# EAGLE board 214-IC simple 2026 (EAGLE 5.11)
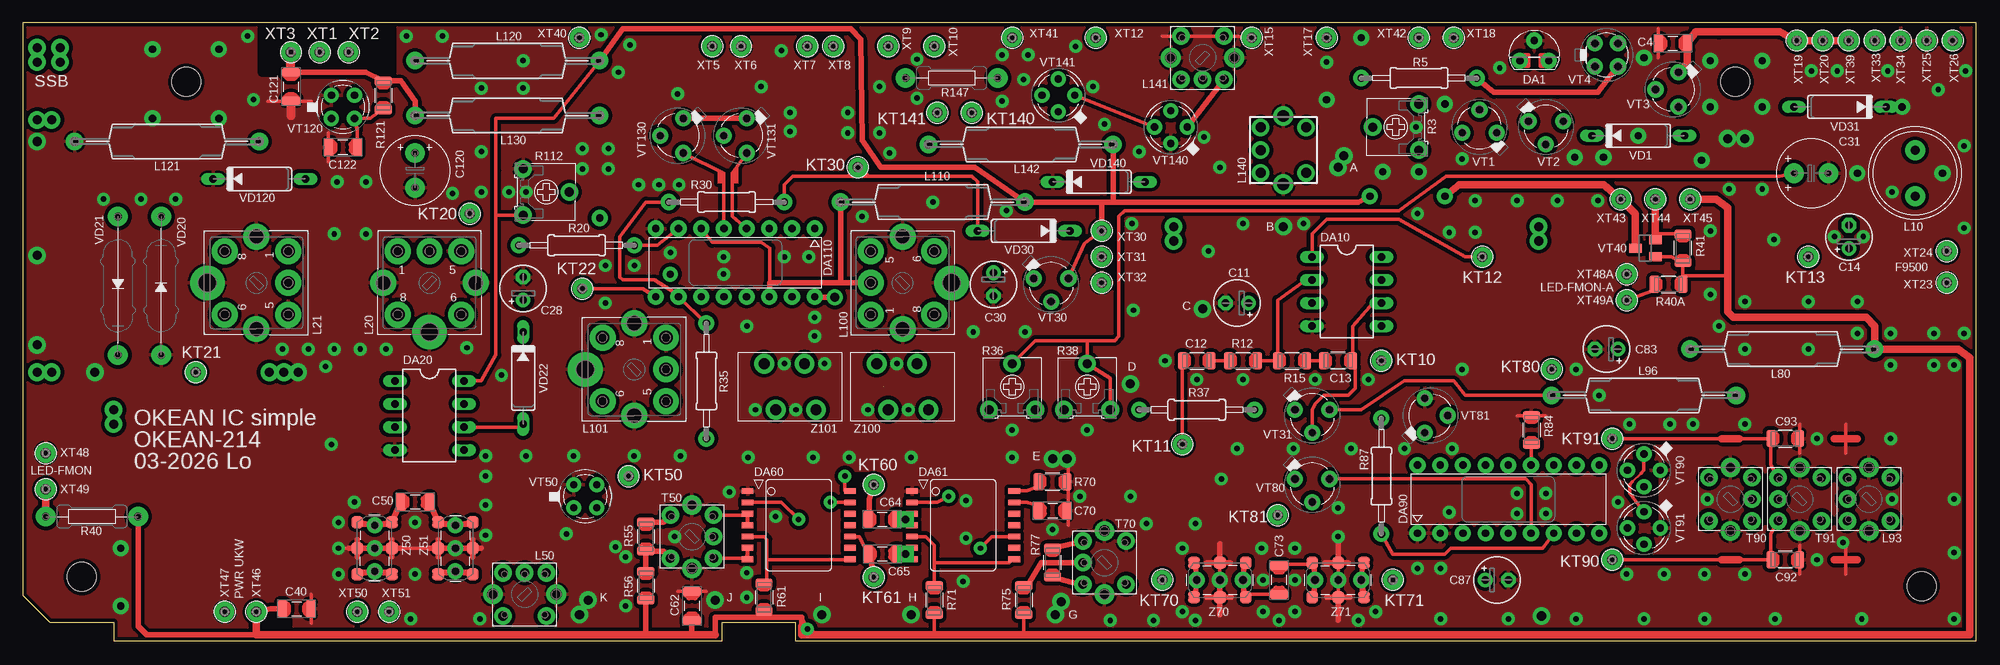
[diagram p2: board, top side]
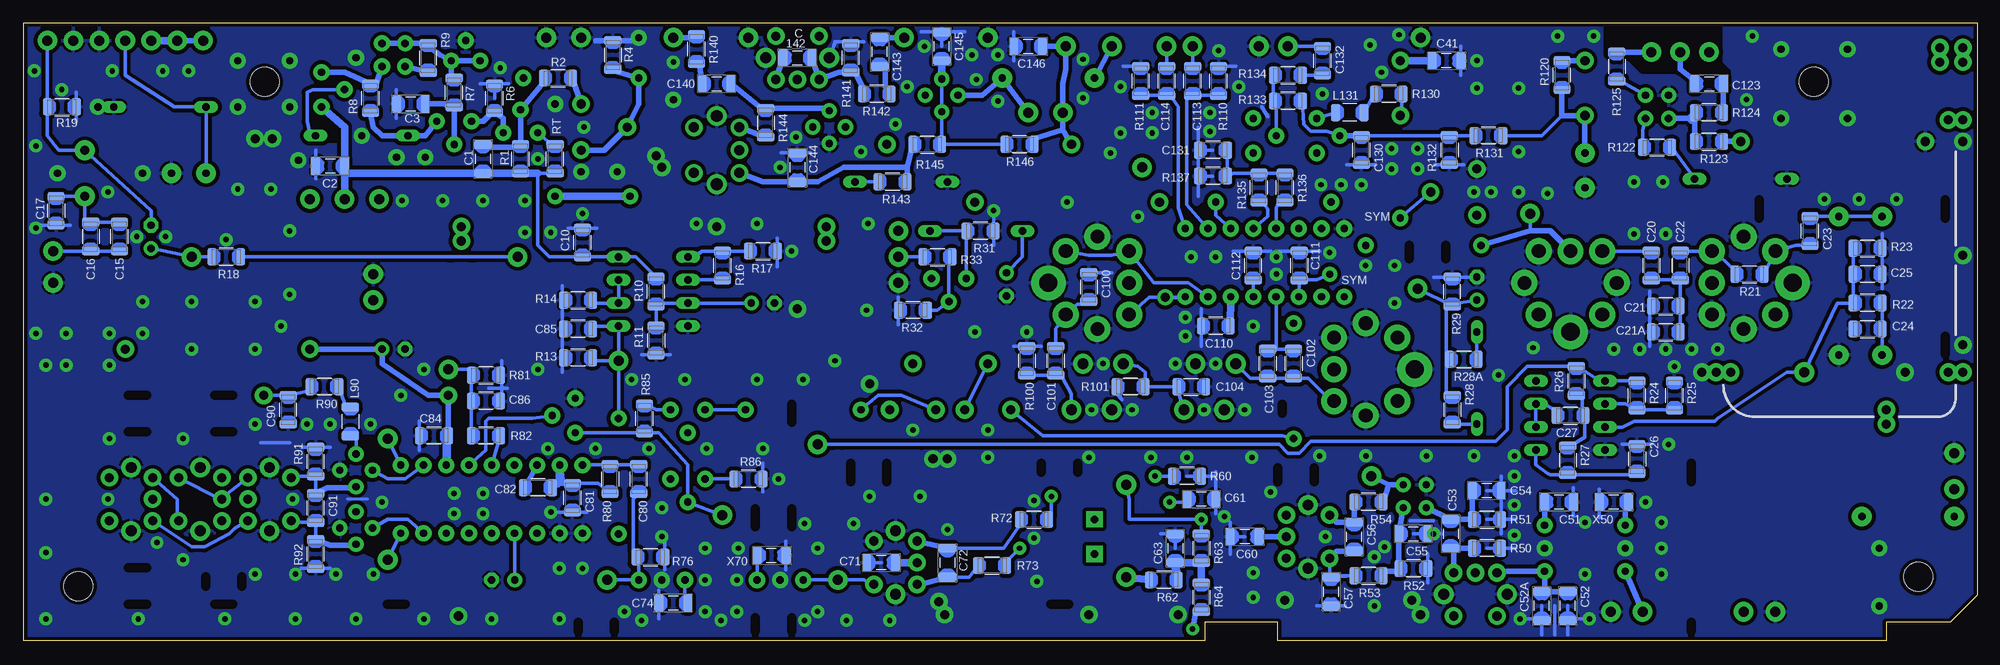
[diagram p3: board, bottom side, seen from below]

Size 215 x 68 mm. Coordinates in mm from the lower left corner, seen from the top.
Outline: 3,2 10,2 10,0 77,0 77,2 85,2 85,0 215,0 215,68 0,68 0,5 3,2
Copper layers (1*16): Top 0.035mm / dielectric 1.5mm / Bottom 0.035mm
Design rules "default *": minimum track width 10mil, minimum drill 24mil, track to track 8mil, track to pad 8mil, pad to pad 8mil, via to via 8mil, smd to smd 8mil, copper to edge 8mil, drill to drill 8mil, minimum pad ring 10mil, minimum via ring 8mil, stop-mask expansion 4mil, vias tented up to drill 0mil, thermal gap 10mil
Holes 3.2 mm at 6.5,7 18,61.5 188.5,61.5 209,6
tRestrict: area 85,29.5 to 87,31.5; area 81.9,24.4 to 83.8,26.4; area 97.4,29.5 to 99.4,31.5; area 94.2,24.4 to 96.3,26.4; 21 lines
bRestrict: 75 lines

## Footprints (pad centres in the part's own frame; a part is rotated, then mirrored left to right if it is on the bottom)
RC-SMD-UNIV = smd 0.965 x 1.93: P$1 -1.587,0; P$2 1.587,0
C1206 = smd 1 x 1.905: 1 -1.587,0; 2 1.587,0
E2,5-5 = drill 0.813 pad 1.6 round: + -1.27,0 | drill 0.813 pad 1.6 octagon: - 1.27,0
C-ELKO-038-075 = drill 0.8 pad 2.184 round: P$1 -1.905,0; P$2 1.905,0
TO92 = drill 0.8 pad 1.778 round: 1 -1.587,-0.635; 2 0,1.587; 3 1.587,-0.635
DIL08 = drill 0.813 long: 1 -3.81,-3.81; 2 -1.27,-3.81; 3 1.27,-3.81; 4 3.81,-3.81; 5 3.81,3.81; 6 1.27,3.81; 7 -1.27,3.81; 8 -3.81,3.81
401.14-5M-FP = smd 0.635 x 1.27: P$1 -3.75,-5.625; P$2 -2.5,-5.625; P$3 -1.25,-5.625; P$4 0,-5.625; P$5 1.25,-5.625; P$6 2.5,-5.625; P$7 3.75,-5.625; P$8 3.75,5.625; P$9 2.5,5.625; P$10 1.25,5.625; P$11 0,5.625; P$12 -1.25,5.625; P$13 -2.5,5.625; P$14 -3.75,5.625
174XA-CERDIP-18 = drill 0.8 pad 1.778 round: P$1 -10,-3.75; P$2 -7.5,-3.75; P$3 -5,-3.75; P$4 -2.5,-3.75; P$5 0,-3.75; P$6 2.5,-3.75; P$7 5,-3.75; P$8 7.5,-3.75; P$9 10,-3.75; P$10 10,3.75; P$11 7.5,3.75; P$12 5,3.75; P$13 2.5,3.75; P$14 0,3.75; P$15 -2.5,3.75; P$16 -5,3.75; P$17 -7.5,3.75; P$18 -10,3.75
174XA2-CERDIP-16 = drill 0.8 pad 1.778 round: P$1 -8.75,-3.75; P$2 -6.25,-3.75; P$3 -3.75,-3.75; P$4 -1.25,-3.75; P$5 1.25,-3.75; P$6 3.75,-3.75; P$7 6.25,-3.75; P$8 8.75,-3.75; P$9 8.75,3.75; P$10 6.25,3.75; P$11 3.75,3.75; P$12 1.25,3.75; P$13 -1.25,3.75; P$14 -3.75,3.75; P$15 -6.25,3.75; P$16 -8.75,3.75
SE11 = drill 1.1 pad 2.159 round: MP 0,0
TOKO-RB10 = drill 1 pad 2.184 round: P$1 2.54,0; P$2 -2.54,0
L-12-10 = drill 1.5 pad 2.852 round: 1 3.493,-3.493; 3 0,-3.493; 5 -3.493,-3.493; 6 -3.493,3.493; 8 3.493,3.493; 11 -5.08,0; 14 5.08,0 | drill 2 pad 3.81 round: 15 0,5.397
L-7-MM = drill 1 pad 1.93 round: 1 -2.381,-2.381; 2 0,-2.381; 3 2.381,-2.381; 4 2.381,2.381; 5 -2.381,2.381 | drill 1.2 pad 2.184 round: P$6 3.493,0; P$7 -3.493,0
0309/20-RUSS = drill 1 pad 1.93 round: 1 -10.16,0; 2 10.16,0
L1206 = smd 1 x 1.905: 1 -1.587,0; 2 1.587,0
71-5 = drill 1.1 pad 1.93 round: 1 2.5,-2.5; 2 2.5,2.5; 3 0,2.5; 4 -2.5,2.5; 5 -2.5,-2.5 | drill 1.3 pad 2.184 round: S1 -3.75,0; S2 3.75,0
R1206 = smd 1 x 1.905: 1 -1.587,0; 2 1.587,0
CA6-V = drill 1 pad 1.93 round: A 2.54,-2.54; E -2.54,-2.54; S 0,2.54
0207/12 = drill 0.813 pad 1.778 round: 1 -6.35,0; 2 6.35,0
R-10 = drill 0.8 pad 2.184 round: P$1 -5.08,0; P$2 5.08,0
DO07 = drill 0.813 long: A 5.08,0; C -5.08,0
VD-OLD-GLASS = drill 0.8 pad 2.184 round: P$1 -7.62,0; P$2 7.62,0
VT-TO-18-3 = drill 0.8 pad 1.778 round: 1 1.905,-0.635; 2 0,1.905; 3 -1.905,-0.635
VT-TO-18-4 = drill 0.8 pad 1.778 round: 1 1.27,-1.27; 2 1.27,1.27; 3 -1.27,1.27; 4 -1.27,-1.27
SOT23 = smd 1 x 1.4: 1 -0.95,-1.1; 2 0.95,-1.1; 3 0,1.1
TO72B = drill 0.8 pad 1.676 round: B 1.27,-1.27; C 1.27,1.27; E -1.27,-1.27; GEH -1.27,1.27
PKF-10700-U-N = drill 0.8 pad 1.778 round: P$1 -2.54,0; P$4 0,0; P$7 2.54,0 | smd 1.27 x 1.27: P$2 -2.857,-1.905; P$3 -2.857,1.905; P$5 0,-1.905; P$6 0,1.905; P$8 2.857,-1.905; P$9 2.857,1.905
FP1P1-60 = drill 1.2 pad 2.184 round: 1 -2.54,2.54; 2 3.175,-2.54; 3 1.905,2.54; 4 -1.27,-2.54

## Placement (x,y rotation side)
C1  [RC-SMD-UNIV]  164.47,53.02 90 bottom
C2  [RC-SMD-UNIV]  181.29,52.23 180 bottom
C3  [RC-SMD-UNIV]  172.4,59.05 180 bottom
C4  [RC-SMD-UNIV]  181.61,65.72 0 top
C10  [C1206]  153.52,43.82 90 bottom
C11  [E2,5-5]  133.67,37.15 180 top
C12  [C1206]  129.22,30.8 0 top
C13  [C1206]  144.78,30.8 180 top
C14  [E2,5-5]  200.99,44.44 90 top
C15  [C1206]  204.47,44.45 90 bottom
C16  [C1206]  207.65,44.45 270 bottom
C17  [C1206]  211.46,47.31 270 bottom
C20  [C1206]  35.88,41.27 270 bottom
C21  [C1206]  34.29,36.83 0 bottom
C21A  [C1206]  34.29,33.97 0 bottom
C22  [C1206]  32.7,41.27 270 bottom
C23  [C1206]  18.41,45.09 90 bottom
C24  [C1206]  12.06,34.29 0 bottom
C25  [C1206]  12.06,40.32 180 bottom
C26  [C1206]  37.47,20 270 bottom
C27  [C1206]  44.77,24.77 0 bottom
C28  [E2,5-5]  55.09,38.74 90 top
C30  [E2,5-5]  106.84,39.21 270 top
C31  C-ELKO-038-075  [C-ELKO-038-075]  196.85,51.44 180 top
C40  [RC-SMD-UNIV]  30.16,3.49 180 top
C41  [RC-SMD-UNIV]  58.42,63.82 0 bottom
C50  [RC-SMD-UNIV]  43.18,15.24 0 top
C51  [RC-SMD-UNIV]  46.04,15.24 180 bottom
C52  [RC-SMD-UNIV]  45.09,3.81 270 bottom
C52A  [RC-SMD-UNIV]  47.94,3.81 270 bottom
C53  [RC-SMD-UNIV]  57.94,11.75 270 bottom
C54  [RC-SMD-UNIV]  53.98,16.51 180 bottom
C55  [RC-SMD-UNIV]  62.07,11.75 0 bottom
C56  [RC-SMD-UNIV]  68.58,11.43 90 bottom
C57  [RC-SMD-UNIV]  71.12,5.4 90 bottom
C60  [RC-SMD-UNIV]  80.64,11.43 0 bottom
C61  [RC-SMD-UNIV]  85.41,15.56 0 bottom
C62  [RC-SMD-UNIV]  73.66,3.81 270 top
C63  [RC-SMD-UNIV]  88.27,10.16 90 bottom
C64  [RC-SMD-UNIV]  94.61,13.34 180 top
C65  [RC-SMD-UNIV]  94.61,9.53 0 top
C70  [RC-SMD-UNIV]  113.35,14.29 180 top
C71  [RC-SMD-UNIV]  120.65,8.57 0 bottom
C72  [RC-SMD-UNIV]  113.35,8.57 90 bottom
C73  [RC-SMD-UNIV]  138.27,6.67 90 top
C74  [RC-SMD-UNIV]  143.51,4.13 180 bottom
C80  [C1206]  147.32,17.78 90 bottom
C81  [C1206]  154.62,15.72 90 bottom
C82  [C1206]  158.43,16.83 180 bottom
C83  [E2,5-5]  174.31,32.07 180 top
C84  [C1206]  169.86,22.54 180 bottom
C85  [C1206]  153.99,34.29 180 bottom
C86  [C1206]  164.15,26.35 180 bottom
C87  [E2,5-5]  162.24,6.67 0 top
C90  [C1206]  185.9,25.4 90 bottom
C91  [C1206]  182.88,14.61 90 bottom
C92  [C1206]  193.99,8.89 180 top
C93  [C1206]  193.99,22.23 0 top
C100  [C1206]  97.79,38.89 270 bottom
C101  [C1206]  101.44,30.8 270 bottom
C102  [C1206]  75.25,30.48 270 bottom
C103  [C1206]  78.11,30.48 270 bottom
C104  [C1206]  86.52,27.94 0 bottom
C110  [C1206]  83.82,34.61 180 bottom
C111  [C1206]  74.61,41.27 90 bottom
C112  [C1206]  79.69,41.27 90 bottom
C113  [C1206]  86.36,61.59 90 bottom
C114  [C1206]  89.22,61.59 90 bottom
C120  C-ELKO-038-075  [C-ELKO-038-075]  43.18,51.75 90 top
C121  [RC-SMD-UNIV]  29.53,60.96 270 top
C122  [RC-SMD-UNIV]  35.24,54.29 0 top
C123  [RC-SMD-UNIV]  29.53,61.28 180 bottom
C130  [C1206]  67.79,53.98 90 bottom
C131  [C1206]  84.14,53.98 180 bottom
C132  [C1206]  72.07,63.82 90 bottom
C140  [RC-SMD-UNIV]  138.75,61.28 180 bottom
C142  [RC-SMD-UNIV]  129.86,64.14 180 bottom
C143  [RC-SMD-UNIV]  120.82,64.78 270 bottom
C144  [RC-SMD-UNIV]  129.86,52.07 90 bottom
C145  [RC-SMD-UNIV]  113.98,65.41 90 bottom
C146  [RC-SMD-UNIV]  104.46,65.41 0 bottom
DA1  [TO92]  166.37,64.45 0 top
DA10  [DIL08]  145.73,38.42 270 top
DA20  [DIL08]  44.77,24.77 270 top
DA60  175-UV-4-FP  [401.14-5M-FP]  85.41,12.7 270 top
DA61  175-UV-4-FP  [401.14-5M-FP]  103.5,12.7 270 top
DA90  [174XA-CERDIP-18]  163.51,15.56 0 top
DA110  [174XA2-CERDIP-16]  78.42,41.59 180 top
KT10  SE11  [SE11]  149.54,30.8 270 top
KT11  SE11  [SE11]  127.64,21.59 0 top
KT12  SE11  [SE11]  160.66,42.23 0 top
KT13  SE11  [SE11]  196.53,42.23 0 top
KT20  SE11  [SE11]  49.21,46.99 90 top
KT21  SE11  [SE11]  19.05,29.53 270 top
KT22  SE11  [SE11]  61.6,38.74 0 top
KT30  SE11  [SE11]  91.92,52.07 0 top
KT50  SE11  [SE11]  66.67,18.1 270 top
KT60  SE11  [SE11]  93.66,17.14 0 top
KT61  SE11  [SE11]  93.66,6.99 0 top
KT70  SE11  [SE11]  125.41,6.67 90 top
KT71  SE11  [SE11]  150.81,6.67 270 top
KT80  SE11  [SE11]  168.28,29.84 90 top
KT81  SE11  [SE11]  138.12,13.81 0 top
KT90  SE11  [SE11]  174.94,8.89 90 top
KT91  SE11  [SE11]  174.94,22.23 90 top
KT140  SE11  [SE11]  104.46,58.1 0 top
KT141  SE11  [SE11]  100.65,58.1 0 top
L10  [TOKO-RB10]  208.28,51.44 270 top
L20  [L-12-10]  44.77,39.37 180 top
L21  [L-12-10]  25.72,39.37 90 top
L50  [L-7-MM]  55.24,5.08 180 top
L80  [0309/20-RUSS]  193.68,32.07 180 top
L90  [L1206]  179.07,24.13 270 bottom
L93  [L-7-MM]  203.2,15.56 270 top
L96  [0309/20-RUSS]  178.44,26.99 0 top
L100  [L-12-10]  96.84,39.37 270 top
L101  [L-12-10]  67.31,29.84 90 top
L110  [0309/20-RUSS]  100.17,48.26 180 top
L120  [0309/20-RUSS]  53.34,63.82 180 top
L121  [0309/20-RUSS]  15.88,54.93 180 top
L130  [0309/20-RUSS]  53.34,57.78 0 top
L131  [L1206]  69.06,58.1 180 bottom
L140  71-5-24153  [71-5]  138.75,53.98 90 top
L141  [L-7-MM]  129.86,64.14 0 top
L142  [0309/20-RUSS]  109.86,54.61 180 top
R1  [R1206]  160.34,53.02 90 bottom
R2  [R1206]  156.21,61.91 0 bottom
R3  [CA6-V]  151.13,56.52 90 top
R4  [R1206]  150.18,64.45 270 bottom
R5  [0207/12]  153.67,61.91 180 top
R6  [R1206]  163.19,59.69 90 bottom
R7  [R1206]  167.64,60.33 90 bottom
R8  [R1206]  176.85,59.69 90 bottom
R9  [R1206]  170.5,64.14 90 bottom
R10  [R1206]  145.41,38.42 90 bottom
R11  [R1206]  145.41,33.02 270 bottom
R12  [R1206]  134.3,30.8 0 top
R13  [R1206]  153.99,31.11 180 bottom
R14  [R1206]  153.99,37.47 0 bottom
R15  [R1206]  139.7,30.8 0 top
R16  [R1206]  138.11,41.27 90 bottom
R17  [R1206]  133.67,42.86 0 bottom
R18  [R1206]  192.72,42.23 180 bottom
R19  [R1206]  210.82,58.74 0 bottom
R20  [0207/12]  60.96,43.5 180 top
R21  [R1206]  25.08,40.32 0 bottom
R22  [R1206]  12.06,37.15 180 bottom
R23  [R1206]  12.06,43.18 0 bottom
R24  [R1206]  37.47,26.99 90 bottom
R25  [R1206]  33.34,26.99 90 bottom
R26  [R1206]  44.13,28.57 270 bottom
R27  [R1206]  45.08,19.84 270 bottom
R28  [R1206]  57.78,25.4 270 bottom
R28A  [R1206]  56.52,30.95 0 bottom
R29  [R1206]  57.78,38.41 90 bottom
R30  [0207/12]  77.47,48.26 0 top
R31  [R1206]  109.7,45.09 180 bottom
R32  [R1206]  117.16,36.35 180 bottom
R33  [R1206]  114.46,42.23 0 bottom
R35  [0207/12]  75.25,28.57 270 top
R36  [CA6-V]  108.9,27.94 0 top
R37  [0207/12]  129.22,25.4 0 top
R38  [CA6-V]  117.16,27.94 0 top
R40  R-10  [R-10]  7.62,13.65 0 top
R40A  [R1206]  181.15,39.21 0 top
R41  [R1206]  182.73,43.18 90 top
R50  [R1206]  53.98,10.16 180 bottom
R51  [R1206]  53.98,13.34 0 bottom
R52  [R1206]  62.07,7.94 180 bottom
R53  [R1206]  66.99,7.14 0 bottom
R54  [R1206]  66.99,15.24 180 bottom
R55  [R1206]  68.58,11.43 270 top
R56  [R1206]  68.58,6.03 270 top
R60  [R1206]  87,18.1 180 bottom
R61  [R1206]  81.6,4.76 270 top
R62  [R1206]  89.53,6.67 180 bottom
R63  [R1206]  85.41,10.16 270 bottom
R64  [R1206]  85.41,4.76 270 bottom
R70  [R1206]  113.35,17.46 180 top
R71  [R1206]  100.33,4.45 270 top
R72  [R1206]  103.82,13.34 0 bottom
R73  [R1206]  108.43,8.26 0 bottom
R75  [R1206]  110.17,4.45 270 top
R76  [R1206]  146.05,9.21 0 bottom
R77  [R1206]  113.35,8.57 90 top
R80  [R1206]  150.5,17.78 270 bottom
R81  [R1206]  164.15,29.21 0 bottom
R82  [R1206]  164.15,22.54 180 bottom
R84  [R1206]  166.05,23.18 270 top
R85  [R1206]  146.69,24.45 90 bottom
R86  [R1206]  135.25,17.78 180 bottom
R87  [0207/12]  149.54,18.1 270 top
R90  [R1206]  181.93,27.94 180 bottom
R91  [R1206]  182.88,19.68 90 bottom
R92  [R1206]  182.88,9.53 90 bottom
R100  [R1206]  104.62,30.8 270 bottom
R101  [R1206]  93.19,27.94 180 bottom
R110  [R1206]  83.5,61.59 90 bottom
R111  [R1206]  92.08,61.59 90 bottom
R112  [CA6-V]  57.63,49.37 270 top
R120  [R1206]  45.72,62.23 90 bottom
R121  [R1206]  39.69,60.01 270 top
R122  [R1206]  35.24,54.29 0 bottom
R123  [R1206]  29.53,54.93 0 bottom
R124  [R1206]  29.53,58.1 180 bottom
R125  [R1206]  39.69,63.18 270 bottom
R130  [R1206]  64.77,60.17 180 bottom
R131  [R1206]  53.82,55.56 180 bottom
R132  [R1206]  58.1,53.98 270 bottom
R133  [R1206]  75.88,59.37 180 bottom
R134  [R1206]  75.88,62.23 0 bottom
R135  [R1206]  79.06,49.85 90 bottom
R136  [R1206]  76.2,49.85 90 bottom
R137  [R1206]  84.14,51.12 180 bottom
R140  [R1206]  140.97,65.09 90 bottom
R141  [R1206]  123.99,64.15 90 bottom
R142  [R1206]  121.13,60.17 180 bottom
R143  [R1206]  119.38,50.48 180 bottom
R144  [R1206]  133.35,56.99 270 bottom
R145  [R1206]  115.57,54.61 0 bottom
R146  [R1206]  105.41,54.61 180 bottom
R147  R-10  [R-10]  102.23,61.91 180 top
RT  [R1206]  156.53,53.02 90 bottom
T50  [L-7-MM]  73.66,11.43 90 top
T70  [L-7-MM]  119.06,8.57 270 top
T90  [L-7-MM]  187.96,15.56 90 top
T91  [L-7-MM]  195.58,15.56 270 top
VD1  KD503  [DO07]  177.8,55.56 0 top
VD20  [VD-OLD-GLASS]  15.24,39.05 90 top
VD21  [VD-OLD-GLASS]  10.48,39.05 270 top
VD22  KD503  [DO07]  55.09,28.89 270 top
VD30  KD503  [DO07]  110.17,45.09 180 top
VD31  KD503  [DO07]  200.03,58.74 180 top
VD120  KD503  [DO07]  26.04,50.8 0 top
VD140  KD503  [DO07]  118.43,50.48 0 top
VT1  [VT-TO-18-3]  160.34,56.52 0 top
VT2  [VT-TO-18-3]  167.64,56.52 180 top
VT3  [VT-TO-18-3]  181.61,60.64 90 top
VT4  [VT-TO-18-4]  174.31,64.45 270 top
VT30  [VT-TO-18-3]  113.19,39.21 180 top
VT31  [VT-TO-18-3]  141.92,24.77 180 top
VT40  BSS84  [SOT23]  178.6,43.18 90 top
VT50  [TO72B]  61.91,15.88 0 top
VT80  [VT-TO-18-3]  141.92,17.14 180 top
VT81  [VT-TO-18-3]  154.94,24.77 270 top
VT90  KT3128  [TO72B]  178.44,18.73 225 top
VT91  KT3128  [TO72B]  178.44,12.38 225 top
VT120  [TO72B]  35.24,58.74 0 top
VT130  [VT-TO-18-3]  72.07,55.56 90 top
VT131  [VT-TO-18-3]  79.06,55.56 90 top
VT140  [TO72B]  126.36,56.52 135 top
VT141  [TO72B]  113.98,60.01 135 top
X50  [RC-SMD-UNIV]  40.01,15.24 0 bottom
X70  [RC-SMD-UNIV]  132.72,9.37 0 bottom
XT1  SE11  [SE11]  32.7,64.77 270 top
XT2  SE11  [SE11]  35.88,64.77 270 top
XT3  SE11  [SE11]  29.53,64.77 270 top
XT5  SE11  [SE11]  75.88,65.41 90 top
XT6  SE11  [SE11]  79.06,65.41 90 top
XT7  SE11  [SE11]  86.36,65.41 90 top
XT8  SE11  [SE11]  89.22,65.41 90 top
XT9  SE11  [SE11]  95.25,65.41 90 top
XT10  SE11  [SE11]  100.33,65.41 90 top
XT12  SE11  [SE11]  118.11,66.36 90 top
XT15  SE11  [SE11]  135.25,66.36 90 top
XT17  SE11  [SE11]  143.51,66.36 90 top
XT18  SE11  [SE11]  157.48,66.36 90 top
XT19  SE11  [SE11]  195.26,66.04 0 top
XT20  SE11  [SE11]  198.12,66.04 90 top
XT23  SE11  [SE11]  211.77,39.37 0 top
XT24  SE11  [SE11]  211.77,42.86 0 top
XT25  SE11  [SE11]  209.55,66.04 180 top
XT26  SE11  [SE11]  212.41,66.04 180 top
XT30  SE11  [SE11]  118.75,45.09 0 top
XT31  SE11  [SE11]  118.75,42.23 0 top
XT32  SE11  [SE11]  118.75,39.37 0 top
XT33  SE11  [SE11]  203.84,66.04 90 top
XT34  SE11  [SE11]  206.69,66.04 90 top
XT39  SE11  [SE11]  200.98,66.04 0 top
XT40  SE11  [SE11]  61.28,66.36 90 top
XT41  SE11  [SE11]  108.9,66.36 180 top
XT42  SE11  [SE11]  153.67,66.36 90 top
XT43  SE11  [SE11]  175.9,48.58 270 top
XT44  SE11  [SE11]  179.71,48.58 90 top
XT45  SE11  [SE11]  183.51,48.58 270 top
XT46  SE11  [SE11]  25.72,3.17 0 top
XT47  SE11  [SE11]  22.23,3.17 135 top
XT48  SE11  [SE11]  2.54,20.64 45 top
XT48A  SE11  [SE11]  176.54,40.33 0 top
XT49  SE11  [SE11]  2.54,16.67 0 top
XT49A  SE11  [SE11]  176.54,37.47 0 top
XT50  SE11  [SE11]  36.83,3.17 270 top
XT51  SE11  [SE11]  40.32,3.17 180 top
Z50  [PKF-10700-U-N]  38.73,10.16 90 top
Z51  [PKF-10700-U-N]  47.62,10.16 270 top
Z70  [PKF-10700-U-N]  131.76,6.67 0 top
Z71  [PKF-10700-U-N]  144.78,6.67 0 top
Z100  [FP1P1-60]  96.52,27.94 0 top
Z101  [FP1P1-60]  84.14,27.94 0 top

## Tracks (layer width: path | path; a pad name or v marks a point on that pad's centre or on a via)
AGND  (via drill 0.6 pad 1.42, 0.8 pad 1.78, 1 pad 1.93)  (2 unrouted)
  Top 0.406: 33.66,55.88 C122.P$1 33.66,52.7 | 31.75,59.37 C121.P$2 26.99,59.37 | 180.02,67.31 C4.P$1 180.02,64.14 | 31.75,1.91 C40.P$1 31.75,5.08 | 34.29,10.16 Z50.P$6 | Z50.P$5 43.02,10.16 Z51.P$5 | 49.53,9.21 Z51.P$6 | 115.1,19.05 115.1,15.88 115.1,12.7 | 125.42,66.52 133.84,66.52 135.26,66.36 | 164.48,24.77 167.65,24.77 | 195.59,7.3 195.59,10.48 | 195.59,20.64 195.59,23.81 | 72.08,5.4 75.25,5.4 | 200.67,20.64 200.67,23.81 | 200.67,7.3 200.67,10.48
  Top 0.61: Z50.P$6 36.83,9.21 | Z50.P$6 36.83,11.11 | Z50.P$5 40.64,9.21 | Z50.P$5 40.64,11.11 | Z51.P$5 45.72,9.21 | Z51.P$5 45.72,11.11 | 49.53,9.21 Z51.P$6 | Z51.P$6 49.53,11.11 | 39.69,10.16 Z50.P$5 | Z50.P$5 41.59,10.16 | Z50.P$6 35.88,10.16 | Z50.P$6 37.78,10.16 | Z51.P$6 50.48,10.16 | Z51.P$6 48.58,10.16 | Z51.P$5 44.77,10.16 | Z51.P$5 46.67,10.16 | Z70.P$5 131.77,2.86 | Z70.P$4 131.77,5.08 131.45,4.76 130.34,4.76 | 130.34,4.76 132.88,4.76 | 132.88,4.76 133.04,4.76 | Z70.P$6 131.77,10.64 | 130.34,8.57 132.88,8.57 | 130.34,4.76 132.88,4.76 | Z71.P$5 143.52,4.76 | Z71.P$5 146.06,4.76 | 143.36,8.57 145.9,8.57 | Z71.P$6 144.79,10.8 | 144.79,2.22 Z71.P$5
  Top 1.016: C121.P$2 29.53,57.78
  Bottom 0.305: 177.16,15.56 179.39,15.56
  Bottom 0.406: 163.19,59.69 R6.2 | 83.82,13.97 C61.P$2 84.45,15.56 | 82.23,9.53 C60.P$1 80.64,11.43 | 120.65,8.57 C71.P$1 | 150.18,65.41 R4.1 | 88.27,10.16 C63.P$2 89.85,11.75 | 85.72,48.9 R137.2 | R137.2 C131.2 | C131.2 85.72,56.52 | C131.2 84.14,53.98 | R137.2 84.14,51.12 | R110.2 81.6,63.18 | R111.2 93.98,63.18 | 72.39,42.86 C111.2 77.15,42.86 | 77.79,42.86 C112.2 81.92,42.86 | 85.41,36.51 C110.2 85.41,32.38 | C145.P$2 111.44,66.99 | C145.P$2 116.2,66.99 | 113.98,65.41 C145.P$2 | 10.48,41.75 10.48,41.59 | 10.48,41.75 10.48,44.77 | 10.48,38.74 10.48,41.75 | 36.04,32.39 36.04,35.4 | 36.04,35.4 | 36.04,35.4 | 36.04,35.4 36.04,38.42 | 103.03,32.39 106.05,32.39 | 118.74,34.77 118.74,37.79 | 108.27,43.51 108.27,46.68 | 56.52,52.39 59.69,52.39 | 66.2,52.39 69.38,52.39 | 56.84,62.23 56.84,65.41 | 106.05,63.82 106.05,67 | 122.56,65.89 125.74,65.89 | 126.37,64.14 125.74,65.73 | 128.44,53.66 131.61,53.66 | 161.62,61.28 164.79,61.28 | 174,57.47 174,60.65 | 209.25,57.15 209.25,60.33 | 209.88,45.72 213.06,45.72 | 181.3,7.94 184.48,7.94 | 181.3,21.27 184.48,21.27 | 185.75,21.75 188.93,21.75 | 171.46,20.96 171.46,24.13 | 162.41,27.62 162.41,25.56 | 162.41,27.62 162.41,28.74 | 162.41,27.62 162.41,28.74 | 162.41,28.74 162.41,30.8 | 161.78,27.78 163.84,27.78 | 153.04,14.13 156.22,14.13 | 144.47,7.78 144.47,10.96 | 133.68,16.35 133.68,19.53 | 145.11,2.38 145.11,5.56 | 132.09,41.12 132.09,44.29 | 155.74,39.05 155.74,35.88 155.74,32.7 155.74,29.53 | 143.84,31.43 147.01,31.43 | 131.14,7.78 131.14,10.95 | 83.83,18.1 87,18.1 | 83.83,15.4 83.83,18.57 | 82.24,9.84 82.24,13.02 | 69.54,3.81 72.71,3.81 | 60.49,6.35 60.49,9.53 | 58.9,11.75 62.08,11.75 | 59.85,13.18 62.39,13.18 | 50.8,10.16 53.98,10.16 | 50.8,13.34 53.98,13.34
  Bottom 0.406: 50.8,16.51 53.98,16.51 | 52.39,11.75 52.39,14.92 52.39,18.1 | 47.95,0.64 47.95,3.81 | 45.09,0.64 45.09,3.81 | 46.52,0.64 46.52,3.81 | 44.45,13.65 44.45,16.83 | 41.59,13.49 41.59,16.67 | 151.93,45.41 155.11,45.41 | 47.15,2.38 v50.33,2.38 | 42.87,2.38 45.72,2.38 | 78.11,57.63 78.74,58.74 | 95.26,40.48 98.27,40.48 | 182.89,50.8 182.89,53.98 | 35.88,21.59 39.05,21.59 | 55.4,40.01 59.85,40.01 | 94.77,27.15 94.14,26.51 R101.2
  Bottom 0.61: 147.96,66.04 R4.1 152.08,66.04
  other vias: 21.59,57.47 14.29,57.47 21.59,65.09 178.44,64.14 170.81,53.18 143.51,59.53 10.79,10.16 14.29,65.09 144.78,52.07 167.16,2.7 10.79,3.81 185.74,63.82 191.45,63.82 177.8,55.56 185.74,58.74 191.45,58.74 184.78,52.86 145.41,53.34 173.99,53.18 189.55,55.24 187.64,55.24 72.07,60.17 81.28,60.96 84.45,58.1 90.81,58.1 77.15,42.23 77.15,40.32 83.82,42.23 86.52,42.23 67.31,41.27 71.28,42.7 72.23,50.16 70.01,50.16 64.14,37.15 79.69,34.61 87.15,35.56 100.17,48.26 92.39,46.67 90.8,55.88 94.3,60.96 95.41,53.66 108.27,47.31 64.45,51.91 64.14,41.27 34.61,50.48 37.78,50.48 37.15,32.07 34.29,32.07 40.01,32.07 13.02,48.58 31.43,32.07 8.89,48.58 16.83,48.58 28.57,32.07 83.82,30.48 61.59,54.13 55.4,49.37 61.59,51.91 50.48,49.37 47.31,49.21 1.59,54.93 96.2,30.48 85.09,25.4 97.47,25.4 88.27,30.48 93.03,25.4 189.55,23.81 183.83,23.81 181.29,23.81 176.85,23.81 176.53,7.3 180.66,7.3 185.1,7.3 189.55,7.3 200.34,10.79 197.49,8.89 205.74,15.56 197.49,22.23 80.64,25.4 164.47,16.19 164.47,13.97 167.64,16.19 167.64,13.97 175.58,15.24 185.42,15.56 34.29,44.77 37.78,44.77 53.5,49.37 67.79,50.16 138.75,45.56 129.86,36.51 121.92,28.26 113.35,20 114.94,20 114.3,4.29 113.67,2.86 97.79,2.86 87.95,2.86 61.28,2.86 62.23,4.45 76.2,4.45 50.48,53.82 50.48,60.8 55.09,60.8 55.09,63.82 42.23,66.52 24.76,66.52 25.4,59.53 83.5,64.93 66.83,65.56 98.43,63.98 107.79,64.45 115.89,65.41 110.17,61.75 107.79,59.37 117.79,60.96 119.06,56.83 122.87,53.82 130.02,55.4 131.76,52.07 143.51,63.66 153.36,56.52 158.44,53.02 140.97,45.88 134.31,45.88 104.62,33.97 122.08,45.88 130.49,42.86 153.52,46.99 157.01,44.93 159.87,44.93 159.87,48.42 164.47,48.42 168.91,48.42 173.36,48.42 187.81,49.69 191.46,49.69 185.74,45.08 185.74,38.1 189.55,37.31 186.7,34.61 201.94,33.81 201.94,37.31 196.54,37.31 205.59,33.81 210.35,33.81 213.69,33.81 212.57,30.32 210.35,30.32 205.59,30.32 212.57,15.55 212.57,9.68 212.57,2.38 185.11,2.38 163.52,2.38 178.44,2.38 170.98,2.38 173.51,26.99 170.97,29.85 158.43,29.85 157.32,21.11 152.08,21.11 146.21,21.11 142.24,28.73 139.86,21.11 133.67,21.11 131.92,17.78 144.78,11.43 144.78,14.6 153.51,7.94 156.05,7.94 157,14.13 136.52,6.67 140.02,6.67 140.02,10.16 136.36,10.16 127.63,10.16 127.63,3.17 136.52,3.17 140.02,3.17 148.91,3.17 156.05,2.38 147,2.22 138.27,2.22 129.06,2.22 124.46,2.22 119.69,2.22 123.66,12.86 129.06,12.86 116.36,15.87 113.34,12.22 103.5,6.51 103.82,11.27 103.82,15.4 82.86,13.65 108.9,20.16 97.79,20.16 90.96,20.16 79.85,20.16 86.99,20.16 77.78,16.35 79.69,7.46 79.69,4.76 66.35,3.81 66.35,9.21 50.95,14.92 50.95,18.1 50.95,11.59 59.84,11.75 72.38,20.32 67.3,20.32 60.64,20.32 55.4,20.32 50.95,20.32 110.33,33.97 122.24,36.35 108.9,23.18 117.16,23.18 52.7,29.21 36.5,15.24 43.17,13.02 43.17,7.3 42.7,2.38 34.76,13.02 34.76,7.3 34.76,10.16 98.43,59.69 94.3,55.88 63.66,66.68 87.15,33.5 84.45,56.04 64.45,54.13 110.65,64.45 196.54,32.07 189.55,32.07 205.59,22.22 202.41,2.38 192.88,2.38 48.89,32.23 65.56,62.55 46.2,66.52 71.75,11.43 65.24,10.32 153.67,51.59 201.93,51.43 211.3,51.43 206.85,58.74 205.27,62.71 199.71,62.71 196.86,62.71 213.84,62.71 210.83,60.64 213.69,54.45 213.69,45.4 205.75,49.37 202.57,44.45 199.4,44.45 192.73,44.13 162.56,63.02 134.31,28.73 129.22,28.73 125.73,30.8 121.92,15.87 149.7,51.59 156.53,59.05 147.32,66.36 30.32,29.53 7.94,29.53 148.11,28.73 33.34,30.16 33.97,21.59 1.59,32.54 1.59,42.39
  pour Top (isolate 0.406): 10,0 10,2 3,2 0,5 0,68 215,68 215,0 85,0 85,2 77,2 77,0
  pour Bottom (isolate 0.406): 10,0 10,2 3,2 0,5 0,68 215,68 215,0 85,0 85,2 77,2 77,0
AGND1  (via drill 1 pad 1.93)
  Bottom 0.406: v166.85,43.97 v166.85,45.56
AGND2  (via drill 1 pad 1.93)
  Bottom 0.406: v126.68,43.97 v126.68,45.56
AGND3  (via drill 1 pad 1.93)
  Bottom 0.406: v27.15,29.53 v28.73,29.53
AGND4  (via drill 1 pad 1.93)
  Bottom 0.406: v10,23.81 v10,25.4
AGND5  (via drill 1 pad 1.93)
  Bottom 0.406: v1.59,29.53 v3.17,29.53
AGND6  (via drill 1 pad 1.93)
  Bottom 0.406: v1.59,57.31 v3.17,57.31
AGND7  (via drill 1 pad 1.93)
  Bottom 0.406: v1.59,63.66 v1.59,65.25
AGND8  (via drill 1 pad 1.93)
  Bottom 0.406: v4.13,63.66 v4.13,65.25
N$1
  Top 0.61: C50.P$1 Z50.P$8 Z50.P$7 Z50.P$9
  Bottom 0.61: Z50.P$7 38.73,14.61 X50.P$2
N$2
  Bottom 0.406: R111.1 C114.1 88.58,59.69 87.95,58.74 87.95,47.62 DA110.P$1
N$3
  Bottom 0.406: DA90.P$8 172.72,13.34 174.94,13.34 VT91.B
N$4
  Top 0.406: DA110.P$9 68.26,38.73 63.5,38.73 KT22.MP
  Bottom 0.406: R29.1 KT22.MP | R29.1 57.31,37.15 C28.+ | R29.1 58.42,36.51 58.42,31.59 R28A.1 58.42,31.43 58.42,27.3 R28.1
N$5
  Bottom 0.406: DA90.P$11 173.04,17.78 174.94,17.78 VT90.B
N$6
  Bottom 0.406: R110.1 C113.1 87,59.69 87,47.94 DA110.P$2
N$7
  Bottom 0.61: R4.2 150.18,63.18 149.54,62.55 R5.2 | 147.32,59.05 R3.S 151.13,53.98 R3.E | 147.32,59.05 R5.2 | 147.32,59.05 R5.2
N$8
  Bottom 0.406: C113.2 XT7.MP
N$9
  Bottom 0.406: C114.2 XT8.MP
N$10
  Top 0.61: VT130.1 VT131.1
  Bottom 0.406: L131.2 VT130.1
N$11
  Bottom 0.406: L131.1 66.52,59.85 R130.2
N$12
  Bottom 0.406: L130.2 R130.1
N$13
  Top 0.406: VT130.3 77.15,51.44 DA110.P$5
  Bottom 0.406: DA110.P$5 77.16,47.63 77,47.95 R136.1
N$14
  Top 0.406: VT131.3 78.11,51.44 78.11,46.67 DA110.P$4
  Bottom 0.406: R135.1 78.43,47.95 78.11,47.47 78.11,46.67 DA110.P$4
N$15
  Top 0.406: R30.1 68.58,48.26 65.72,44.45 65.72,40.01 66.04,39.69 69.53,39.69 71.75,38.26 DA110.P$10 R35.1
N$16
  Bottom 0.406: C131.1 R137.1 81.92,51.44 R135.2 R136.2
N$17
  Bottom 0.406: R134.1 R133.2 77.15,59.21 VT131.2
N$18
  Bottom 0.406: R133.1 74.14,56.83 73.34,56.04 71.6,56.04 VT130.2 | C130.2 R132.1 R131.2
  Bottom 0.61: C130.2 VT130.2
N$19
  Bottom 0.406: C132.1 R134.2
N$20
  Bottom 0.406: C132.2 XT5.MP
N$21
  Bottom 0.61: C146.P$2 XT10.MP 100.33,62.87 100.65,61.28 KT141.MP 100.65,56.2 | L142.2 100.65,56.2 | R146.1 103.82,55.24 100.65,56.2
N$22
  Bottom 0.61: L121.1 R123.2
N$23
  Bottom 0.406: DA90.P$4 160.97,11.11 C87.+
N$24
  Top 0.406: DA110.P$6 75.88,43.81 81.28,43.81 82.23,43.18 82.23,39.37
  Top 0.61: DA110.P$14 82.23,39.37 90.01,39.37 | 90.01,39.37 L100.3 | 90.01,39.37 90.02,46.67 L110.2
  Bottom 0.813: C110.1 DA110.P$14
N$25
  Bottom 0.406: VT3.2 182.88,60.64 183.2,60.64 183.83,60.33 183.83,57.15 183.51,55.88 VD1.A
N$26
  Bottom 0.406: DA110.P$13 C112.1
N$27
  Bottom 0.406: Z101.2 C104.1 R101.1 91.6,29.53 92.39,30.16 Z100.1
N$28
  Bottom 0.61: R8.1 176.53,56.52 175.58,55.56 VD1.C 170.81,55.56 VT2.3
N$29
  Bottom 0.406: C102.1 77.15,32.07 | 77.15,32.07 C103.1 | 77.15,32.07 DA110.P$12
N$30
  Bottom 0.406: VD22.C 55.09,31.59 R28A.2
N$31
  Bottom 0.406: L101.5 71.12,26.35 73.66,28.89 C102.2 C103.2 80.01,28.89 Z101.1
N$32  (via drill 1 pad 1.78)
  Top 0.61: v89.38,37.78 87.16,37.78
  Bottom 0.406: v89.38,37.78 DA110.P$16 86.68,37.63 v89.38,37.78 | v89.38,37.78 91.12,37.78 L100.1
N$33
  Bottom 0.406: DA110.P$15 86.84,39.37 90.65,39.37 L100.5 95.26,42.39 97.8,42.39 L100.6
N$34
  Bottom 0.406: Z100.2 99.69,27.15 100.65,28.89 C101.2 R100.2
N$35
  Bottom 0.406: VD120.A R122.2
N$36
  Bottom 0.406: R35.2 76.52,22.54 102.87,22.54 R36.E
N$37  (via drill 0.6 pad 1.42)
  Top 0.406: v90.49,18.1 90.49,16.51 DA60.P$14
  Bottom 0.406: R60.2 v90.49,18.1
N$38
  Bottom 0.406: XT26.MP R19.1 212.41,55.56 211.14,53.98 L10.P$2 200.98,47.31 C14.-
N$39
  Top 0.406: DA90.P$7 167.32,10.16 157.16,10.16 156.53,9.53 150.81,9.53 R87.2
N$40
  Bottom 0.406: R18.2 KT13.MP C14.+
N$41
  Top 0.406: R20.1 68.9,43.5 69.85,43.5 DA110.P$7
N$42
  Top 0.406: VT40.2 179.71,44.6 179.88,44.77 R41.2 | R41.2
  Top 0.813: XT44.MP VT40.2
  Bottom 0.406: DA10.8 157.16,42.23 158.43,43.5 158.43,51.12 158.43,51.44 RT.1 | DA10.8 147.64,42.23 145.73,40.32 R10.2 | C10.1 DA10.8
  Bottom 0.61: 179.71,51.59 C2.P$1
  Bottom 0.813: 158.43,51.44 R1.1 C1.P$1 179.71,51.44 | 179.71,51.44 179.71,51.59 C2.P$1 179.71,56.52 VT3.3 | 179.71,51.44 XT44.MP
N$43
  Bottom 0.406: 49.21,45.09 KT20.MP
  Bottom 0.61: L20.3 46.99,45.09 49.21,45.09 R20.2
N$44
  Bottom 0.406: VT30.1 R31.2 | R31.2 | R31.2 VD30.C
N$46
  Top 0.61: VT140.E L141.3
  Bottom 0.61: L141.3 C142.P$2
N$47
  Bottom 0.406: R33.2 113.19,41.91 VT30.2 114.46,36.35 R32.1
N$48
  Top 0.406: R70.2 111.44,17.46 111.44,16.83 110.49,16.51 108.9,16.51 109.54,16.51 DA61.P$14
N$49
  Top 0.406: R30.2 83.82,50.16 84.77,51.12 93.19,51.12 | 93.19,51.12 94.14,51.12 104.46,51.12 105.09,50.48 VD30.A | 93.19,51.12 KT30.MP | KT30.MP 90.81,51.12 KT30.MP
  Bottom 0.406: R30.2 83.82,46.83 DA110.P$3 | VD30.A 105.09,42.23 | 105.09,42.23 | 105.09,42.23 C30.+
N$50
  Bottom 0.406: KT80.MP 166.05,29.84 R81.1 C86.2 R82.2
N$51
  Top 0.254: 177.16,17.46 178.12,18.41
  Top 0.406: VT91.E 176.85,16.19 176.85,17.14 177.16,17.46 | VT90.E 178.44,18.73 178.12,18.41
  Bottom 0.406: VT90.E 178.44,22.23 L90.2
N$52
  Bottom 0.61: R2.2 | R3.A R2.2 | R2.2
N$53
  Bottom 0.61: DA1.1 DA1.3 | R7.2 167.96,61.91 167.96,62.23 DA1.3 | VT4.3 VT4.4 R9.2 170.03,65.09 169.24,64.46 DA1.3
N$54
  Bottom 0.61: VT2.1 164.47,57.15 163.83,57.78 R6.1 162.24,57.47 VT1.1
N$55
  Top 0.61: VT4.2 173.35,60.33 168.91,60.33 161.93,60.33 R5.1
  Top 0.813: XT39.MP XT20.MP XT19.MP 193.36,66.99 186.69,66.99 184.15,66.99 C4.P$2 183.2,63.5 VT3.1
  Bottom 0.61: VT3.1 181.61,62.55 179.71,62.55 R8.2 176.21,61.28 VT4.2 | XT19.MP XT39.MP
  Bottom 0.813: XT20.MP XT39.MP
N$56
  Bottom 0.61: VT2.2 R7.1 168.28,58.74 168.59,59.05 C3.P$1
N$57
  Bottom 0.61: R140.2 141.6,66.36 XT17.MP
N$58
  Bottom 0.61: C1.P$2 163.51,54.29 160.97,54.29 R1.2 VT1.2 157.8,61.44 R2.1
N$59
  Bottom 0.61: VT140.B 126.84,58.58 R144.1 133.83,58.58 C140.P$1
N$60
  Bottom 0.61: C142.P$1 L141.1 125.26,62.55 R141.1 123.36,62.23 122.72,60.96 R142.2
N$61
  Top 0.406: Z71.P$7 Z71.P$9
  Top 0.61: Z71.P$8 Z71.P$7
  Bottom 0.406: C80.1 147.96,15.56 147.96,9.84 R76.1 147.32,8.57 Z71.P$7 148.91,6.67 KT71.MP
N$62
  Top 0.406: Z71.P$2 Z71.P$1 Z71.P$3 141.61,8.41 139.07,8.41 C73.P$2
  Bottom 0.406: C74.P$1 142.24,4.76 Z71.P$1
N$63
  Bottom 0.813: R64.1 R63.2 | R63.2 C63.P$1 | R63.2 C63.P$1 | C63.P$1 R62.1 88.27,6.99 C63.P$1
N$64
  Top 0.406: Z70.P$9 Z70.P$7 Z70.P$8 134.63,5.08 C73.P$1
  Bottom 0.406: Z70.P$7 X70.P$1
N$65
  Top 0.406: C65.P$1 92.71,10.16 92.08,11.43 DA60.P$10
  Top 0.61: KT61.MP 93.34,9.21 C65.P$1
  Bottom 0.813: R62.2 KT61.MP
N$66
  Top 0.406: R61.1 81.92,6.67 81.92,8.89 | 81.92,8.89 81.92,11.11 | 81.92,11.11 81.6,11.43 | 81.6,11.43 80.33,11.43 79.69,11.43 DA60.P$5 81.6,11.43 | 81.92,11.11 81.6,11.43 | 81.92,8.89 81.92,11.11 | 81.92,8.89 91.12,8.89 DA60.P$8
N$67
  Top 0.61: T50.4 70.48,13.02 C56.P$2
  Bottom 0.61: T50.4 70.48,13.02 C56.P$2 R54.2
N$68
  Top 0.406: VT141.E VT140.C
N$69
  Bottom 0.61: R144.2 L140.2
N$70
  Top 0.61: Z51.P$8 Z51.P$7 Z51.P$9
  Bottom 0.61: C52.P$1 C52A.P$1 47.62,5.71 47.62,6.03 Z51.P$7 51.75,7.62 L50.3
N$71
  Top 0.406: T50.3 79.86,13.81 79.86,13.97 79.69,13.97 DA60.P$4 DA60.P$3
N$72
  Top 0.406: T50.1 79.7,9.05 79.7,9.21 79.69,9.21 DA60.P$6 DA60.P$7
N$73
  Bottom 0.61: C140.P$2 140.65,63.5 R140.1
N$74
  Top 0.406: L96.1 158.75,26.99 157.48,28.57 152.08,28.57 147.32,25.4 VT31.3
  Bottom 0.406: VT31.3 145.41,25.4 146.05,25.72 R85.2
  Bottom 0.61: DA90.P$12 168.59,20 168.59,21.59 168.28,19.68 C84.1 L96.1 170.5,26.99 175.58,30.48 C83.+ L80.2
N$75
  Bottom 0.406: C20.1 L20.1
N$76
  Bottom 0.406: C22.1 L21.1 28.89,42.86 26.99,40.96 26.99,40.64 R21.1
N$77  (via drill 0.6 pad 1.42)
  Top 0.406: v88.9,15.24 90.49,15.24 91.12,15.24 DA60.P$13
  Bottom 0.406: C61.P$1 87.31,15.24 87.63,15.24 v88.9,15.24
N$78
  Bottom 0.61: L50.1 57.63,10.16 | 57.63,10.16 C53.P$2 57.63,10.16 | 57.63,10.16 R50.2
N$79
  Bottom 0.61: C54.P$2 R51.1 C53.P$1 VT50.E
N$80
  Top 0.406: DA61.P$5 99.38,11.43 100.33,10.48 100.33,8.57 | 100.33,8.57 R71.1 100.33,8.57 | 100.33,8.57 108.58,8.57 108.9,8.89 DA61.P$8
N$81
  Bottom 0.406: C20.2 C22.2 C21.2 C21A.2
N$82
  Bottom 0.406: R21.2 23.5,40.64 23.18,40.96 22.23,42.86 20,43.5 C23.1
N$83
  Bottom 0.61: R124.1 C123.P$1
N$84
  Bottom 0.406: C23.2 VD20.P$2 VD21.P$1
N$85
  Bottom 0.406: VD21.P$2 C24.2 R22.1
N$86
  Bottom 0.406: R23.1 C25.2 R22.2 15.4,37.15 KT21.MP 20.95,29.53 28.57,24.45 28.89,24.13 37.78,24.13 39.05,23.5 DA20.3
N$88
  Top 0.406: Z70.P$3 Z70.P$1 Z70.P$2
  Bottom 0.406: Z70.P$1 KT70.MP 122.56,6.67 T70.4
N$89
  Bottom 0.406: T90.5 184.78,13.02 C91.1 R92.2
  Bottom 0.61: VT91.C 179.07,10.48 181.29,10.48 R92.2
N$90
  Bottom 0.406: C91.2 R91.1 184.78,18.1 T90.4
  Bottom 0.61: VT90.C 179.07,16.83 181.61,16.83 C91.2
N$91
  Top 0.406: T91.1 192.41,19.37 192.41,20.64 C93.1 188.91,22.23 187.01,22.23 KT91.MP
  Top 0.813: 187.01,22.23 188.91,22.23
  Bottom 0.406: DA90.P$10 KT91.MP
N$92
  Top 0.406: 192.41,10.79 C92.2 192.09,8.89 188.91,8.89 187.01,8.89 KT90.MP | 192.41,10.79 192.41,11.11 192.41,10.79 | 192.41,10.79 192.41,11.75 T91.3
  Top 0.813: 187.01,8.89 188.91,8.89
  Bottom 0.406: KT90.MP DA90.P$9
N$93
  Bottom 0.406: L93.3 196.53,10.32 195.1,10.32 192.41,11.75 191.77,12.38 T90.1
N$94
  Bottom 0.406: T91.4 198.12,13.97 198.12,15.56 L93.1
N$95
  Bottom 0.406: T90.3 193.36,15.56 | 193.36,15.56 | 193.36,15.56 T91.5
N$96
  Bottom 0.406: L90.1 179.71,26.04 R90.1
N$97
  Bottom 0.406: R90.2 183.67,27.46 183.83,27.46 C90.2 186.06,26.99 L96.2
N$98
  Bottom 0.406: DA90.P$18 153.03,19.37 R80.1 C80.2
N$99
  Bottom 0.406: R80.2 151.76,17.3 C81.2
  Bottom 0.61: 156.21,19.05 DA90.P$17 | 156.21,19.05 156.21,17.14 C82.1 | 156.21,19.05 155.89,19.05 155.73,17.62 156.06,17.3 C81.2
N$100
  Bottom 0.61: DA90.P$16 159.7,17.14 C82.2
N$101
  Bottom 0.406: DA90.P$14 R82.1
N$102
  Top 0.406: DA90.P$13 R84.2
  Bottom 0.406: VT81.2 159.07,24.45 163.83,24.45 164.15,24.13 164.15,20.95 DA90.P$13
N$103
  Bottom 0.406: VT81.1 R85.1 145.1,22.86 141.92,19.37 141.92,18.57 VT80.2 KT81.MP
N$104
  Bottom 0.406: R86.2 139.38,17.78 VT80.1
N$105
  Top 0.61: C50.P$2 Z51.P$2 Z51.P$1 Z51.P$3
  Bottom 0.61: Z51.P$1 C51.P$2
N$106
  Top 0.61: C121.P$1 37.78,62.55 R121.1 41.59,61.59 43.18,59.37 L130.1
  Top 1.016: C121.P$1 XT3.MP
  Bottom 0.406: R131.1 47.94,55.56 45.72,57.78
  Bottom 0.61: C120.P$2 L130.1 45.72,57.78 R120.1
N$107
  Top 0.406: DA90.P$6 166.05,17.14 165.42,17.78 152.4,17.78 VT80.3
N$108
  Bottom 0.406: R37.2 VT31.1
N$109
  Bottom 0.406: R38.E 118.43,26.99 120.97,26.99 R37.1
N$110
  Top 0.406: C31.P$2 193.36,51.12 156.69,51.12 151.45,47.31 121.28,47.31 120.65,46.67 120.65,33.5 120.17,33.02 117.16,33.02 | 117.16,33.02 111.44,33.02 R36.S | 117.16,33.02 R38.S 119.7,28.89 R38.A
  Bottom 0.406: R36.S R36.A | C31.P$2 VD31.A 198.44,58.74 203.84,62.23 XT33.MP
N$111
  Bottom 0.406: R87.1 KT10.MP | KT10.MP DA10.5 152.4,34.61 C85.1 | R13.1 152.4,30.8 KT10.MP
N$112
  Bottom 0.406: R33.1 XT31.MP
N$113
  Top 0.406: KT11.MP C12.1
  Bottom 0.406: R24.2 DA20.1 41.59,28.57 43.5,29.84 R26.1 49.53,30.16 51.75,27.94 51.75,24.13 51.75,23.18 53.02,21.91 73.34,21.91 74.61,20.64 75.88,20.64 76.83,21.59 87.31,21.59 116.2,21.59 124.94,21.59 125.89,21.59 126.21,21.59 KT11.MP
N$114
  Bottom 0.406: DA20.2 38.73,26.04 R24.1 R25.1
N$115
  Top 0.406: DA20.6 54.61,23.5 VD22.A
  Bottom 0.406: DA20.6 DA20.7 47.79,26.04 46.52,25.4 C27.1 | VD22.A R28.2
N$116
  Bottom 0.61: XT12.MP C143.P$1
N$117
  Bottom 0.61: R142.1 120.18,60.96 120.18,63.03 C143.P$2
N$118
  Bottom 0.61: L140.4 133.67,50.48 C144.P$1 127.64,50.48 124.78,52.07 117.79,52.07 | 117.79,52.07 117.79,50.8 R143.1 | 117.79,52.07 R145.1
N$119  (via drill 0.8 pad 1.78)
  Top 0.406: DA20.8 50.48,28.57 52.07,31.43 52.07,46.83 | 52.07,46.83 52.07,51.75 52.07,57.47 58.42,57.47 L120.1 | 52.07,46.83 R112.A | VT30.3 116.84,43.66 117.16,43.97 XT30.MP
  Top 0.61: v148.27,48.9 147,48.26 120.02,48.26 | 118.75,48.26 120.02,48.26 | 118.75,48.26 XT30.MP | 104.78,52.07 | 104.78,52.07 L110.1 118.75,48.26 | 104.78,52.07 | 104.78,52.07 94.46,52.07 92.39,55.09 92.23,66.2 91.12,67.31 66.04,67.31 L120.1 | 120.02,48.26 L142.1
  Top 0.813: v156.53,48.9 158.12,50.16 173.99,50.16 XT43.MP 177.5,46.97 VT40.3
  Bottom 0.813: L120.1 C41.P$1 | v148.27,48.9 v156.53,48.9
N$120
  Bottom 0.406: R26.2 43.5,26.99 43.5,25.4 C27.2 43.18,22.38 44.77,21.43 R27.1
N$121
  Bottom 0.406: C26.2 38.26,18.26 44.77,18.26 R27.2 46.04,18.26 46.99,18.26 47.31,18.41 48.58,19.37 DA20.5
N$122
  Bottom 0.406: R146.2 R145.2 VT141.GEH VT141.B
  Bottom 0.813: VT141.B C145.P$1
N$123
  Top 0.406: C12.2 R12.1
N$124
  Top 0.406: R15.2 C13.2
N$125
  Bottom 0.61: KT140.MP R147.P$1 109.54,60.01 VT141.C
N$126
  Bottom 0.61: R147.P$2 XT9.MP
N$127
  Top 0.406: DA10.6 148.59,37.15 146.37,34.61 C13.1 146.37,30.32 146.69,30 146.69,27.78 145.89,26.99 143.19,26.99 142.24,26.04 141.92,25.4 VT31.2
  Bottom 0.406: DA10.7 DA10.6 152.08,37.15 R14.2
N$128
  Top 0.61: Z50.P$3 Z50.P$1 Z50.P$2
  Bottom 0.61: XT50.MP Z50.P$1
N$129
  Top 0.406: DA10.2 141.29,39.69 138.11,37.47 R15.1 R12.2
  Bottom 0.406: DA10.2 140.97,39.69 138.75,39.69 R16.1
N$130
  Bottom 0.406: C15.1 C16.2 XT24.MP
N$131  (via drill 0.8 pad 1.78)
  Top 0.305: C65.P$2 v97.16,9.53
  Top 0.406: DA61.P$6 97.47,10.16 96.2,10.16 C65.P$2 96.2,8.89 97.79,8.89 DA61.P$7
N$132
  Bottom 0.61: R53.2 65.25,7.62 63.66,7.62 R52.2 C55.P$1 VT50.B
N$133
  Top 0.406: KT12.MP 158.75,42.23 151.45,46.35 143.51,46.35 141.92,44.77 DA10.1
  Bottom 0.406: DA10.1 141.29,42.23 140.34,42.86 R16.2 R17.1 | KT12.MP 165.42,42.23 165.89,42.23 167.8,42.23 168.28,42.23 R18.1
N$134
  Bottom 0.406: R11.1 R10.1 144.46,37.15 DA10.3 C11.+
N$135
  Bottom 0.61: 64.77,17.14 R54.1 | 64.77,17.14 KT50.MP | VT50.C 64.77,17.14
N$136
  Top 0.813: R40.P$1 XT49.MP
N$137
  Bottom 0.406: C17.1 L10.P$1 208.28,46.35 C16.1 C15.2
N$138
  Bottom 0.61: C123.P$2 31.43,61.91 32.7,62.87 XT1.MP
N$139  (via drill 0.6 pad 1.42)
  Top 0.406: 214.31,27.62 214.31,31.11 | 85.72,0.64 v86.36,1.27 85.72,2.54 86.04,0.64 100.33,0.64 R71.2 | 110.17,0.64 R75.2 | 81.6,2.54 R61.2 | VT40.1 181.46,42.23 R41.1 R40A.2 183.05,40.01 182.73,40.17 187.64,40.17
  Top 0.61: 25.72,0.64 13.65,0.64 12.7,1.59 R40.P$2 | 76.2,0.64 76.2,2.54 80.33,2.54 81.6,2.54 85.72,2.54 85.72,1.27 85.72,0.64 | 86.36,0.64 85.72,0.64 | 86.36,0.64 87.31,0.64 | 87.31,0.64 86.68,0.64 85.72,0.64 | v86.36,1.27 86.36,0.64 | v86.36,1.27 86.36,0.64 | v86.36,1.27 87.31,0.64 | 68.58,0.64 R56.2 | 73.66,0.64 C62.P$2 | XT46.MP 27.3,3.49 C40.P$2
  Top 0.813: 85.72,0.64 85.72,1.59 85.72,0.64 | 85.72,0.64 110.17,0.64 214.31,0.64 214.31,26.99 214.31,27.62 214.31,31.11 213.04,32.07 L80.1 203.84,34.61 202.88,35.56 188.28,35.56 187.64,36.2 187.64,40.17 187.64,47.62 186.37,48.58 XT45.MP | 76.2,0.64 73.66,0.64 68.58,0.64 25.72,0.64 XT46.MP
  Bottom 0.61: v86.36,1.27 86.04,3.17 R64.2
N$140
  Top 0.406: R40A.1 179.24,38.42 XT49A.MP
N$141
  Bottom 0.406: C101.1 101.45,34.29 L100.8 99.07,36.99 97.16,36.99 C100.2
N$142  (via drill 0.8 pad 1.78)
  Bottom 0.406: 60.17,49.37 v63.5,46.51
N$143
  Top 0.813: 199.39,22.23 201.93,22.23
N$144
  Top 0.813: 199.39,8.89 201.93,8.89
N$145
  Bottom 0.61: 31.75,57.47 R124.2 | R123.1 31.11,57.15 | 31.11,57.15 | 31.11,57.15 | 31.11,57.15 31.43,57.15 | 31.43,57.15 31.75,57.47 | 31.75,57.47 31.43,57.47 31.43,57.15 | 31.75,57.47 VT120.E
N$146
  Bottom 0.406: RT.2 157.32,54.61 157.32,54.93 VT1.3
N$148
  Top 0.406: R121.2 39.05,58.1 38.26,57.47 VT120.B 36.83,56.2 C122.P$2
  Bottom 0.406: VT120.B 36.83,56.2 C122.P$2
N$149  (via drill 0.8 pad 1.68)
  Bottom 0.406: v71.28,40.32 72.71,39.69 C111.1 DA110.P$11
N$150
  Bottom 0.61: XT2.MP R125.1
N$151
  Bottom 0.406: VT120.C 38.73,61.28 R125.2
N$165
  Bottom 0.61: R9.1 VT4.1
N$172
  Bottom 0.406: R143.2 VD140.A
N$177  (via drill 0.8 pad 1.78)
  Top 0.305: C64.P$1 v97.16,13.34
  Top 0.406: DA61.P$3 97.47,13.97 96.52,13.97 C64.P$1 96.2,12.7 97.47,12.7 DA61.P$4
N$190
  Bottom 0.61: L120.2 R120.2
N$201
  Top 0.406: 167.64,64.45 167,64.45 167,63.18 167.64,63.18
N$205
  Top 0.406: 164.78,64.45 165.74,64.45 165.74,63.18 165.1,63.18
N$221
  Top 0.406: C70.P$2 111.44,14.92 110.49,15.24 109.54,15.24 DA61.P$13
N$222  (via drill 0.6 pad 1.42)
  Top 0.406: v101.92,15.88 100.65,15.24 98.42,15.24 DA61.P$2
  Bottom 0.406: v101.92,15.88 101.92,13.65 R72.2
N$223  (via drill 0.6 pad 1.42)
  Top 0.406: v105.41,10.16 106.68,11.43 108.58,11.43 DA61.P$10
  Bottom 0.406: R73.2 106.68,8.89 v105.41,10.16
N$224
  Top 0.61: T70.3 116.84,6.03 C72.P$1
  Bottom 0.406: R73.1 110.97,6.99 C72.P$1
  Bottom 0.61: C72.P$1 116.84,6.03 T70.3
N$225
  Top 0.61: T70.1 C72.P$2
  Bottom 0.406: 105.41,12.7 107.16,10.16 110.17,10.16 C72.P$2
  Bottom 0.61: C72.P$2 T70.1 | R72.1 105.41,12.7
N$226
  Top 0.61: T50.5 70.48,9.84 R55.2 R56.1
  Bottom 0.406: C57.P$2 R53.1 71.28,7.14 T50.5
  Bottom 0.61: T50.5 70.48,9.84 R55.2
N$227
  Top 0.61: T70.2 115.25,8.57 112.08,8.57 110.81,6.35 R75.1
  Bottom 0.813: T70.2 C71.P$2
N$228  (via drill 0.6 pad 1.42)
  Top 0.406: v85.41,13.34 83.5,15.24 80.33,15.24 DA60.P$2
  Top 0.61: KT60.MP 93.19,15.56 93.19,13.97 C64.P$2
  Bottom 0.406: KT60.MP 93.34,15.56 93.34,13.34 v85.41,13.34 R63.1
N$229
  Bottom 0.61: T50.2 C60.P$2
(copper drawn outside any net)
  shapes: Top area x3

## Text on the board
tPlace: SSB | A | B | F9500 | LED-FMON-A | C | D | OKEAN IC simple | OKEAN-214 | E | LED-FMON | 03-2026 Lo | PWR UKW | K | J | I | H | G
bPlace: C | 142 | SYM | SYM
tNames: GND | OSC EMR | OSC COL | OSC PWR | GND | CAP1 | MIX OSC | GND | MIX RF1 | MIX RF2 | AMP OUT | AMP PWR | CAP2 | AMP FB | MA1 | MA2 | MA3 | ANT IN | AMP IN | CAP3 | UKW PWR | OSC PWR | OSC EMR | OSC COL | scale | 9V PWR IN | 9V PWR AA | S-meter 1 | S-meter 2 | GND PWR | AUDIO
tDocu: 1 | 2 | 3 | 4 | 5 | 6 | 7 | 8 | 9 | 10 | 11 | 12 | 13 | 14 | 15 | 16 | 17 | 18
